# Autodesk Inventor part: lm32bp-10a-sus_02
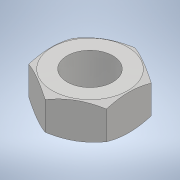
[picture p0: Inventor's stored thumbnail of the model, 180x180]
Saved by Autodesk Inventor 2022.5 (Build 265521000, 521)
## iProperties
Part Number: lm32bp-10a-sus_02
Material: 一般
Document SubType Name: Modeling
Designer: ImaoCorp
Density: 1 g/cm^3
Appearance: 既定
Author: ImaoCorp
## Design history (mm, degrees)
feature "lm32bp-10a-sus_02"
node "ソリッド1"
